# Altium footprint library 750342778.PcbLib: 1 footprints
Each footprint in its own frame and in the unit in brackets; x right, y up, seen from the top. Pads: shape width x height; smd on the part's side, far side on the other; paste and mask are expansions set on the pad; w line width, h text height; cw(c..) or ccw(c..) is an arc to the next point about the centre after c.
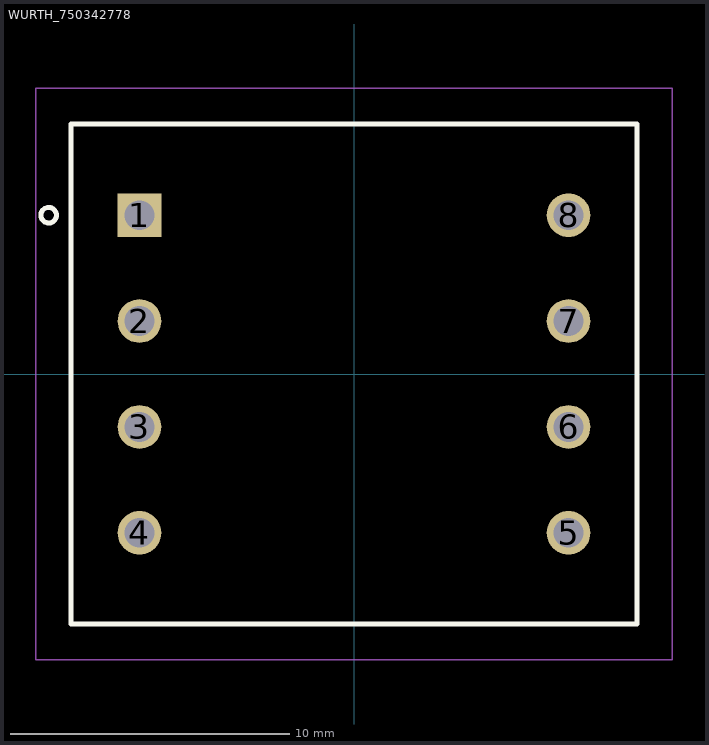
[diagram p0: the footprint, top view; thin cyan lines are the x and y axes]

## WURTH_750342778 [mm] "TRANSFORMER, 3.5mH, 10%, THRU"
height 14.3
pads (8):
  rect 1.57x1.57 / inner round 1.57 / far side rect 1.57x1.57 hole 1.07: 1(-7.7,5.7)
  round 1.57 hole 1.07: 2(-7.7,1.9) 3(-7.7,-1.9) 4(-7.7,-5.7) 5(7.7,-5.7) 6(7.7,-1.9) 7(7.7,1.9) 8(7.7,5.7)
Top Overlay:
  circle w0.178: c-10.959,5.7 r0.279
  lines w0.178: -10.15,-8.98 -10.15,8.98 10.15,8.98 10.15,-8.98 -10.15,-8.98
  text ".Designator" at -1.524,10.668 h1.02
Bottom Overlay:
  lines w0.178: -10.15,-8.305 -10.15,-7.163 ; -10.15,-6.629 -10.15,-5.487 ; -10.15,-4.851 -10.15,-3.709 ; -10.15,-3.2 -10.15,-2.058 ; -10.15,-1.524 -10.15,-0.382 ; -10.15,0.254 -10.15,1.396 ; -10.15,1.905 -10.15,3.047 ; -10.15,3.556 -10.15,4.698 ; -10.15,5.207 -10.15,6.349 ; -10.15,6.883 -10.15,8.025 ; -9.09,-8.98 -7.948,-8.98 ; -9.09,8.98 -7.948,8.98 ; -7.185,-8.98 -6.043,-8.98 ; -7.185,8.98 -6.043,8.98 ; -5.28,-8.98 -4.138,-8.98 ; -5.28,8.98 -4.138,8.98 ; -3.429,-8.98 -2.287,-8.98 ; -3.429,8.98 -2.287,8.98 ; -1.778,-8.98 -0.636,-8.98 ; -1.778,8.98 -0.636,8.98 ; 0,-8.98 1.142,-8.98 ; 0,8.98 1.142,8.98 ; 1.905,-8.98 3.047,-8.98 ; 1.905,8.98 3.047,8.98 ; 3.81,-8.98 4.952,-8.98 ; 3.81,8.98 4.952,8.98 ; 5.715,-8.98 6.857,-8.98 ; 5.715,8.98 6.857,8.98 ; 7.62,-8.98 8.762,-8.98 ; 7.62,8.98 8.762,8.98 ; 10.15,-8.305 10.15,-7.163 ; 10.15,-6.629 10.15,-5.487 ; 10.15,-4.851 10.15,-3.709 ; 10.15,-3.2 10.15,-2.058 ; 10.15,-1.524 10.15,-0.382 ; 10.15,0.254 10.15,1.396 ; 10.15,1.905 10.15,3.047 ; 10.15,3.556 10.15,4.698 ; 10.15,5.207 10.15,6.349 ; 10.15,6.883 10.15,8.025
Mechanical 5:
  circle w0.127: c-10.959,5.7 r0.279
  lines w0.127: -10.15,-8.98 10.15,-8.98 10.15,8.98 -10.15,8.98 -10.15,-8.98
  text ".Designator" at -1.524,-0.508 h1.02
Mechanical 15:
  lines w0.05: -11.42,-10.25 -11.42,10.25 11.42,10.25 11.42,-10.25 -11.42,-10.25
Mechanical 17:
  text "LEAD LENGTH: 3.5MM" at -8.128,-10.287 h1
3D body: height 14.3, standoff 0, extent -10.15,-8.98 10.15,8.98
